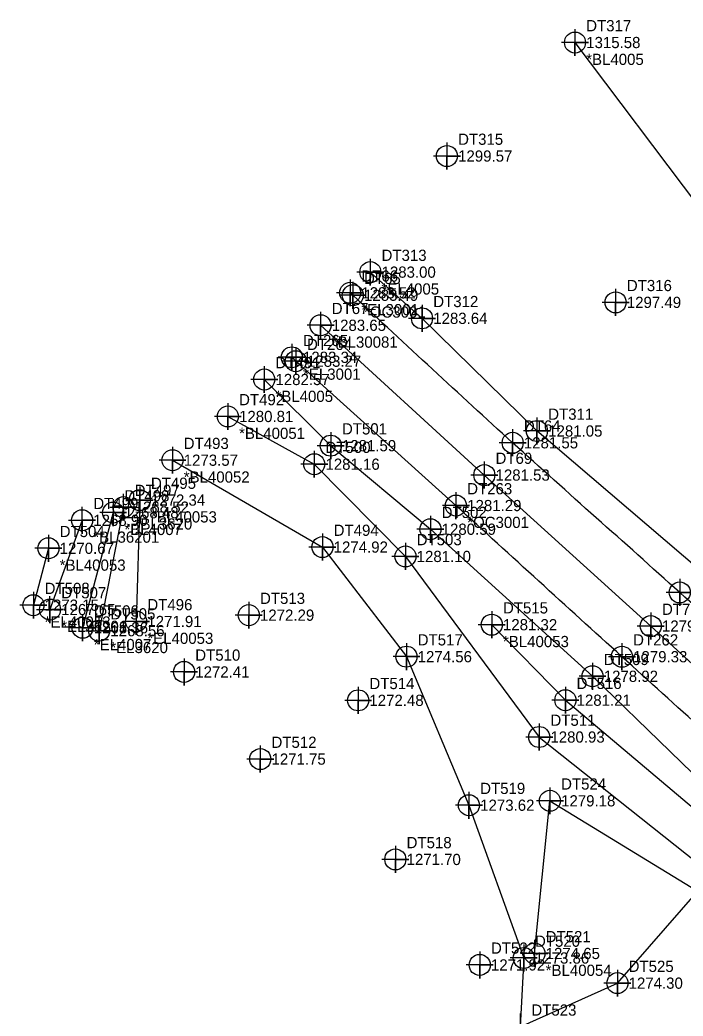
# Model space of a CAD drawing. Extents: x 1391270 to 1392151, y 960049 to 960667.
# Drawn here: x 1391269.8 to 1391417.5, y 960444.8 to 960666.9 of the extents above; entities that cross this region are included whole.
import ezdxf

# ---------------------------------------------------------------- set-up
doc = ezdxf.new("R2010")
doc.units = 0
for name, color, linetype in [('Exist DTM Breakline', 7, 'Continuous'), ('Exist DTM Breakline Cogo Comment', 7, 'Continuous'), ('Exist DTM Breakline Cogo Elevation', 7, 'Continuous'), ('Exist DTM Breakline Cogo Number', 7, 'Continuous'), ('Exist DTM Breakline Cogo Point CELL', 7, 'Continuous'), ('Exist DTM Breakline Underwater', 7, 'Continuous'), ('Exist DTM Breakline Underwater Cogo Comment', 7, 'Continuous'), ('Exist DTM Breakline Underwater Cogo Elevation', 7, 'Continuous'), ('Exist DTM Breakline Underwater Cogo Number', 7, 'Continuous'), ('Exist DTM Breakline Underwater Cogo Point CELL', 7, 'Continuous'), ('Exist DTM Crownline', 7, 'Continuous'), ('Exist DTM Crownline Cogo Comment', 7, 'Continuous'), ('Exist DTM Crownline Cogo Elevation', 7, 'Continuous'), ('Exist DTM Crownline Cogo Number', 7, 'Continuous'), ('Exist DTM Crownline Cogo Point CELL', 7, 'Continuous'), ('Exist DTM Regular Point CELL', 7, 'Continuous'), ('Exist DTM Regular Point Cogo Elevation', 7, 'Continuous'), ('Exist DTM Regular Point Cogo Number', 7, 'Continuous'), ('Exist Hydro Stream or Body of Water', 7, 'Continuous'), ('Exist Hydro Stream or Body of Water Cogo Comment', 7, 'Continuous'), ('Exist Hydro Stream or Body of Water Cogo Elevation', 7, 'Continuous'), ('Exist Hydro Stream or Body of Water Cogo Number', 7, 'Continuous'), ('Exist Hydro Stream or Body of Water Cogo Point CELL', 7, 'Continuous'), ('Exist Roads EOP', 7, 'Continuous'), ('Exist Roads EOP Cogo Comment', 7, 'Continuous'), ('Exist Roads EOP Cogo Elevation', 7, 'Continuous'), ('Exist Roads EOP Cogo Number', 7, 'Continuous'), ('Exist Roads EOP Cogo Point CELL', 7, 'Continuous')]:
    doc.layers.add(name, color=color, linetype=linetype)

msp = doc.modelspace()

# ---------------------------------------------------------------- linework, layer by layer
at = {"layer": 'Exist DTM Breakline'}
for p, q in [((1391296.492, 960559.828), (1391295.697, 960532.764)), ((1391276.164, 960549.078), (1391272.813, 960536.395))]:
    msp.add_line(p, q, dxfattribs=at)
for points in [[(1391393.449, 960661.814), (1391420.927, 960625.274), (1391436.139, 960609.727), (1391454.255, 960579.709), (1391474.064, 960542.237), (1391491.205, 960517.974), (1391488.925, 960510.22), (1391503.285, 960493.748), (1391518.522, 960484.392), (1391548.09, 960503.995), (1391563.385, 960512.482)], [(1391572.148, 960404.532), (1391566.45, 960414.023), (1391560.493, 960420.45), (1391551.134, 960422.515), (1391527.127, 960450.418), (1391519.65, 960459.266), (1391497.478, 960479.87), (1391479.684, 960499.497), (1391463.962, 960505.846), (1391421.736, 960543.837), (1391384.984, 960575.223), (1391359.376, 960600.331), (1391347.861, 960610.635)], [(1391324.233, 960586.705), (1391339.042, 960571.952), (1391361.254, 960553.328), (1391397.359, 960520.55), (1391431.984, 960487.022), (1391447.858, 960468.977), (1391469.387, 960439.951), (1391481.042, 960400.574)], [(1391316.128, 960578.463), (1391335.373, 960567.825), (1391355.688, 960547.259), (1391385.482, 960507.01), (1391423.359, 960476.875), (1391439.432, 960458.285), (1391460.969, 960427.473), (1391472.339, 960397.865), (1391475.509, 960385.212), (1391483.88, 960383.187), (1391486.523, 960363.38), (1391492.773, 960311.276)], [(1391303.798, 960568.714), (1391337.195, 960549.348), (1391355.915, 960524.922), (1391369.834, 960491.808), (1391382.04, 960457.756), (1391381.24, 960442.404), (1391402.896, 960452.148), (1391420.738, 960472.565), (1391439.191, 960450.264), (1391454.114, 960420.78), (1391463.153, 960401.998), (1391468.38, 960380.734), (1391451.764, 960376.78), (1391432.731, 960383.561)], [(1391374.906, 960532.045), (1391391.307, 960515.216), (1391429.365, 960483.152), (1391444, 960465.435), (1391465.005, 960433.545)], [(1391384.425, 960458.766), (1391387.861, 960492.79), (1391420.701, 960472.719)]]:
    msp.add_lwpolyline(points, dxfattribs=at)
at = {"layer": 'Exist DTM Breakline Cogo Point CELL'}
for points in [[(1391393.449, 960664.814), (1391393.449, 960658.814), (1391393.449, 960661.814), (1391396.449, 960661.814), (1391390.449, 960661.814)], [(1391347.861, 960613.635), (1391347.861, 960607.635), (1391347.861, 960610.635), (1391350.861, 960610.635), (1391344.861, 960610.635)], [(1391359.376, 960603.331), (1391359.376, 960597.331), (1391359.376, 960600.331), (1391362.376, 960600.331), (1391356.376, 960600.331)], [(1391324.233, 960589.705), (1391324.233, 960583.705), (1391324.233, 960586.705), (1391327.233, 960586.705), (1391321.233, 960586.705)], [(1391316.128, 960581.463), (1391316.128, 960575.463), (1391316.128, 960578.463), (1391319.128, 960578.463), (1391313.128, 960578.463)], [(1391384.984, 960578.223), (1391384.984, 960572.223), (1391384.984, 960575.223), (1391387.984, 960575.223), (1391381.984, 960575.223)], [(1391339.042, 960574.952), (1391339.042, 960568.952), (1391339.042, 960571.952), (1391342.042, 960571.952), (1391336.042, 960571.952)], [(1391303.798, 960571.714), (1391303.798, 960565.714), (1391303.798, 960568.714), (1391306.798, 960568.714), (1391300.798, 960568.714)], [(1391335.373, 960570.825), (1391335.373, 960564.825), (1391335.373, 960567.825), (1391338.373, 960567.825), (1391332.373, 960567.825)], [(1391296.492, 960562.828), (1391296.492, 960556.828), (1391296.492, 960559.828), (1391299.492, 960559.828), (1391293.492, 960559.828)], [(1391361.254, 960556.328), (1391361.254, 960550.328), (1391361.254, 960553.328), (1391364.254, 960553.328), (1391358.254, 960553.328)], [(1391276.164, 960552.078), (1391276.164, 960546.078), (1391276.164, 960549.078), (1391279.164, 960549.078), (1391273.164, 960549.078)], [(1391337.195, 960552.348), (1391337.195, 960546.348), (1391337.195, 960549.348), (1391340.195, 960549.348), (1391334.195, 960549.348)], [(1391355.688, 960550.259), (1391355.688, 960544.259), (1391355.688, 960547.259), (1391358.688, 960547.259), (1391352.688, 960547.259)], [(1391272.813, 960539.395), (1391272.813, 960533.395), (1391272.813, 960536.395), (1391275.813, 960536.395), (1391269.813, 960536.395)], [(1391295.697, 960535.764), (1391295.697, 960529.764), (1391295.697, 960532.764), (1391298.697, 960532.764), (1391292.697, 960532.764)], [(1391374.906, 960535.045), (1391374.906, 960529.045), (1391374.906, 960532.045), (1391377.906, 960532.045), (1391371.906, 960532.045)], [(1391355.915, 960527.922), (1391355.915, 960521.922), (1391355.915, 960524.922), (1391358.915, 960524.922), (1391352.915, 960524.922)], [(1391397.359, 960523.55), (1391397.359, 960517.55), (1391397.359, 960520.55), (1391400.359, 960520.55), (1391394.359, 960520.55)], [(1391391.307, 960518.216), (1391391.307, 960512.216), (1391391.307, 960515.216), (1391394.307, 960515.216), (1391388.307, 960515.216)], [(1391385.482, 960510.01), (1391385.482, 960504.01), (1391385.482, 960507.01), (1391388.482, 960507.01), (1391382.482, 960507.01)], [(1391387.861, 960495.79), (1391387.861, 960489.79), (1391387.861, 960492.79), (1391390.861, 960492.79), (1391384.861, 960492.79)], [(1391369.834, 960494.808), (1391369.834, 960488.808), (1391369.834, 960491.808), (1391372.834, 960491.808), (1391366.834, 960491.808)], [(1391382.04, 960460.756), (1391382.04, 960454.756), (1391382.04, 960457.756), (1391385.04, 960457.756), (1391379.04, 960457.756)], [(1391384.425, 960461.766), (1391384.425, 960455.766), (1391384.425, 960458.766), (1391387.425, 960458.766), (1391381.425, 960458.766)], [(1391402.896, 960455.148), (1391402.896, 960449.148), (1391402.896, 960452.148), (1391405.896, 960452.148), (1391399.896, 960452.148)], [(1391381.24, 960445.404), (1391381.24, 960439.404), (1391381.24, 960442.404), (1391384.24, 960442.404), (1391378.24, 960442.404)]]:
    msp.add_lwpolyline(points, dxfattribs=at)
for centre in [(1391393.449, 960661.814), (1391347.861, 960610.635), (1391359.376, 960600.331), (1391324.233, 960586.705), (1391316.128, 960578.463), (1391384.984, 960575.223), (1391339.042, 960571.952), (1391303.798, 960568.714), (1391335.373, 960567.825), (1391296.492, 960559.828), (1391361.254, 960553.328), (1391276.164, 960549.078), (1391337.195, 960549.348), (1391355.688, 960547.259), (1391272.813, 960536.395), (1391295.697, 960532.764), (1391374.906, 960532.045), (1391355.915, 960524.922), (1391397.359, 960520.55), (1391391.307, 960515.216), (1391385.482, 960507.01), (1391369.834, 960491.808), (1391387.861, 960492.79), (1391384.425, 960458.766), (1391382.04, 960457.756), (1391402.896, 960452.148)]:
    msp.add_circle(centre, 2.344, dxfattribs=at)
at = {"layer": 'Exist DTM Breakline Underwater'}
msp.add_line((1391290.577, 960557.031), (1391283.765, 960531.369), dxfattribs=at)
at = {"layer": 'Exist DTM Breakline Underwater Cogo Point CELL'}
for points in [[(1391290.577, 960560.031), (1391290.577, 960554.031), (1391290.577, 960557.031), (1391293.577, 960557.031), (1391287.577, 960557.031)], [(1391283.765, 960534.369), (1391283.765, 960528.369), (1391283.765, 960531.369), (1391286.765, 960531.369), (1391280.765, 960531.369)]]:
    msp.add_lwpolyline(points, dxfattribs=at)
for centre in [(1391290.577, 960557.031), (1391283.765, 960531.369)]:
    msp.add_circle(centre, 2.344, dxfattribs=at)
at = {"layer": 'Exist DTM Crownline'}
msp.add_lwpolyline([(1391336.775, 960598.787), (1391373.255, 960565.397), (1391410.328, 960531.742), (1391446.425, 960498.79), (1391483.147, 960465.095), (1391520.03, 960431.473), (1391553.996, 960400.745), (1391556.572, 960398.448)], dxfattribs=at)
at = {"layer": 'Exist DTM Crownline Cogo Point CELL'}
for points in [[(1391336.775, 960601.787), (1391336.775, 960595.787), (1391336.775, 960598.787), (1391339.775, 960598.787), (1391333.775, 960598.787)], [(1391373.255, 960568.397), (1391373.255, 960562.397), (1391373.255, 960565.397), (1391376.255, 960565.397), (1391370.255, 960565.397)], [(1391410.328, 960534.742), (1391410.328, 960528.742), (1391410.328, 960531.742), (1391413.328, 960531.742), (1391407.328, 960531.742)]]:
    msp.add_lwpolyline(points, dxfattribs=at)
for centre in [(1391336.775, 960598.787), (1391373.255, 960565.397), (1391410.328, 960531.742)]:
    msp.add_circle(centre, 2.344, dxfattribs=at)
at = {"layer": 'Exist DTM Regular Point CELL'}
for points in [[(1391364.919, 960639.509), (1391364.919, 960633.509), (1391364.919, 960636.509), (1391367.919, 960636.509), (1391361.919, 960636.509)], [(1391402.503, 960606.894), (1391402.503, 960600.894), (1391402.503, 960603.894), (1391405.503, 960603.894), (1391399.503, 960603.894)], [(1391320.789, 960537.174), (1391320.789, 960531.174), (1391320.789, 960534.174), (1391323.789, 960534.174), (1391317.789, 960534.174)], [(1391306.365, 960524.519), (1391306.365, 960518.519), (1391306.365, 960521.519), (1391309.365, 960521.519), (1391303.365, 960521.519)], [(1391345.154, 960518.187), (1391345.154, 960512.187), (1391345.154, 960515.187), (1391348.154, 960515.187), (1391342.154, 960515.187)], [(1391323.35, 960505.093), (1391323.35, 960499.093), (1391323.35, 960502.093), (1391326.35, 960502.093), (1391320.35, 960502.093)], [(1391353.438, 960482.726), (1391353.438, 960476.726), (1391353.438, 960479.726), (1391356.438, 960479.726), (1391350.438, 960479.726)], [(1391372.231, 960459.21), (1391372.231, 960453.21), (1391372.231, 960456.21), (1391375.231, 960456.21), (1391369.231, 960456.21)]]:
    msp.add_lwpolyline(points, dxfattribs=at)
for centre in [(1391364.919, 960636.509), (1391402.503, 960603.894), (1391320.789, 960534.174), (1391306.365, 960521.519), (1391345.154, 960515.187), (1391323.35, 960502.093), (1391353.438, 960479.726), (1391372.231, 960456.21)]:
    msp.add_circle(centre, 2.344, dxfattribs=at)
at = {"layer": 'Exist Hydro Stream or Body of Water'}
for p, q in [((1391292.872, 960558.252), (1391287.45, 960530.713)), ((1391283.66, 960555.319), (1391276.506, 960535.422))]:
    msp.add_line(p, q, dxfattribs=at)
at = {"layer": 'Exist Hydro Stream or Body of Water Cogo Point CELL'}
for points in [[(1391289.872, 960558.252), (1391295.872, 960558.252), (1391292.872, 960558.252), (1391292.872, 960555.252), (1391292.872, 960561.252)], [(1391280.66, 960555.319), (1391286.66, 960555.319), (1391283.66, 960555.319), (1391283.66, 960552.319), (1391283.66, 960558.319)], [(1391273.506, 960535.422), (1391279.506, 960535.422), (1391276.506, 960535.422), (1391276.506, 960532.422), (1391276.506, 960538.422)], [(1391284.45, 960530.713), (1391290.45, 960530.713), (1391287.45, 960530.713), (1391287.45, 960527.713), (1391287.45, 960533.713)]]:
    msp.add_lwpolyline(points, dxfattribs=at)
for centre in [(1391292.872, 960558.252), (1391283.66, 960555.319), (1391276.506, 960535.422), (1391287.45, 960530.713)]:
    msp.add_circle(centre, 2.344, dxfattribs=at)
at = {"layer": 'Exist Roads EOP'}
msp.add_line((1391343.959, 960605.485), (1391343.365, 960606.024), dxfattribs=at)
msp.add_lwpolyline([(1391366.94, 960558.603), (1391331.255, 960590.777), (1391330.371, 960591.644)], dxfattribs=at)
for points in [[(1391558.507, 960409.653), (1391527.113, 960438.384), (1391489.556, 960472.216), (1391453.007, 960506.097), (1391416.783, 960539.246), (1391379.565, 960572.597), (1391343.959, 960605.485)], [(1391497.16, 960311.857), (1391494.199, 960339.333), (1391490.437, 960370.67), (1391484.795, 960409.189), (1391479.352, 960429.561), (1391471.345, 960448.702), (1391460.843, 960466.873), (1391449.093, 960483.056), (1391440.139, 960491.898), (1391403.899, 960524.912), (1391366.94, 960558.603)]]:
    msp.add_spline(points, degree=3, dxfattribs=at)
at = {"layer": 'Exist Roads EOP Cogo Point CELL'}
for points in [[(1391343.365, 960609.024), (1391343.365, 960603.024), (1391343.365, 960606.024), (1391346.365, 960606.024), (1391340.365, 960606.024)], [(1391343.959, 960608.485), (1391343.959, 960602.485), (1391343.959, 960605.485), (1391346.959, 960605.485), (1391340.959, 960605.485)], [(1391330.371, 960594.644), (1391330.371, 960588.644), (1391330.371, 960591.644), (1391333.371, 960591.644), (1391327.371, 960591.644)], [(1391331.255, 960593.777), (1391331.255, 960587.777), (1391331.255, 960590.777), (1391334.255, 960590.777), (1391328.255, 960590.777)], [(1391379.565, 960575.597), (1391379.565, 960569.597), (1391379.565, 960572.597), (1391382.565, 960572.597), (1391376.565, 960572.597)], [(1391366.94, 960561.603), (1391366.94, 960555.603), (1391366.94, 960558.603), (1391369.94, 960558.603), (1391363.94, 960558.603)], [(1391416.783, 960542.246), (1391416.783, 960536.246), (1391416.783, 960539.246), (1391419.783, 960539.246), (1391413.783, 960539.246)], [(1391403.899, 960527.912), (1391403.899, 960521.912), (1391403.899, 960524.912), (1391406.899, 960524.912), (1391400.899, 960524.912)]]:
    msp.add_lwpolyline(points, dxfattribs=at)
for centre in [(1391343.365, 960606.024), (1391343.959, 960605.485), (1391330.371, 960591.644), (1391331.255, 960590.777), (1391379.565, 960572.597), (1391366.94, 960558.603), (1391416.783, 960539.246), (1391403.899, 960524.912)]:
    msp.add_circle(centre, 2.344, dxfattribs=at)

# ---------------------------------------------------------------- texts
at = {"layer": 'Exist DTM Breakline Cogo Comment'}
for s, p in [('*BL4005', (1391395.949, 960656.814)), ('*EL4005', (1391350.361, 960605.635)), ('*BL4005', (1391326.733, 960581.705)), ('*BL40051', (1391318.628, 960573.463)), ('*BL40052', (1391306.298, 960563.714)), ('*BL40053', (1391298.992, 960554.828)), ('*BL40053', (1391278.664, 960544.078)), ('*EL40053', (1391275.313, 960531.395)), ('*EL40053', (1391298.197, 960527.764)), ('*BL40053', (1391377.406, 960527.045)), ('*BL40054', (1391386.925, 960453.766))]:
    msp.add_text(s, height=2.5, dxfattribs=at).set_placement(p)
at = {"layer": 'Exist DTM Breakline Cogo Elevation'}
for s, p in [('1315.58', (1391395.949, 960660.564)), ('1283.00', (1391350.361, 960609.385)), ('1283.64', (1391361.876, 960599.081)), ('1282.57', (1391326.733, 960585.455)), ('1280.81', (1391318.628, 960577.213)), ('1281.05', (1391387.484, 960573.973)), ('1281.59', (1391341.542, 960570.702)), ('1273.57', (1391306.298, 960567.464)), ('1281.16', (1391337.873, 960566.575)), ('1272.34', (1391298.992, 960558.578)), ('1280.59', (1391363.754, 960552.078)), ('1270.67', (1391278.664, 960547.828)), ('1274.92', (1391339.695, 960548.098)), ('1281.10', (1391358.188, 960546.009)), ('1273.15', (1391275.313, 960535.145)), ('1271.91', (1391298.197, 960531.514)), ('1281.32', (1391377.406, 960530.795)), ('1274.56', (1391358.415, 960523.672)), ('1278.92', (1391399.859, 960519.3)), ('1281.21', (1391393.807, 960513.966)), ('1280.93', (1391387.982, 960505.76)), ('1279.18', (1391390.361, 960491.54)), ('1273.62', (1391372.334, 960490.558)), ('1273.86', (1391384.54, 960456.506)), ('1274.65', (1391386.925, 960457.516)), ('1274.30', (1391405.396, 960450.898))]:
    msp.add_text(s, height=2.5, dxfattribs=at).set_placement(p)
at = {"layer": 'Exist DTM Breakline Cogo Number'}
for s, p in [('DT317', (1391395.949, 960664.314)), ('DT313', (1391350.361, 960613.135)), ('DT312', (1391361.876, 960602.831)), ('DT491', (1391326.733, 960589.205)), ('DT492', (1391318.628, 960580.963)), ('DT311', (1391387.484, 960577.723)), ('DT501', (1391341.542, 960574.452)), ('DT493', (1391306.298, 960571.214)), ('DT500', (1391337.873, 960570.325)), ('DT495', (1391298.992, 960562.328)), ('DT502', (1391363.754, 960555.828)), ('DT504', (1391278.664, 960551.578)), ('DT494', (1391339.695, 960551.848)), ('DT503', (1391358.188, 960549.759)), ('DT508', (1391275.313, 960538.895)), ('DT496', (1391298.197, 960535.264)), ('DT515', (1391377.406, 960534.545)), ('DT517', (1391358.415, 960527.422)), ('DT509', (1391399.859, 960523.05)), ('DT516', (1391393.807, 960517.716)), ('DT511', (1391387.982, 960509.51)), ('DT519', (1391372.334, 960494.308)), ('DT524', (1391390.361, 960495.29)), ('DT520', (1391384.54, 960460.256)), ('DT521', (1391386.925, 960461.266)), ('DT525', (1391405.396, 960454.648)), ('DT523', (1391383.74, 960444.904))]:
    msp.add_text(s, height=2.5, dxfattribs=at).set_placement(p)
at = {"layer": 'Exist DTM Breakline Underwater Cogo Comment'}
for s, p in [('*BL4007', (1391293.077, 960552.031)), ('*EL4007', (1391286.265, 960526.369))]:
    msp.add_text(s, height=2.5, dxfattribs=at).set_placement(p)
at = {"layer": 'Exist DTM Breakline Underwater Cogo Elevation'}
for s, p in [('1268.48', (1391293.077, 960555.781)), ('1268.36', (1391286.265, 960530.119))]:
    msp.add_text(s, height=2.5, dxfattribs=at).set_placement(p)
at = {"layer": 'Exist DTM Breakline Underwater Cogo Number'}
for s, p in [('DT498', (1391293.077, 960559.531)), ('DT506', (1391286.265, 960533.869))]:
    msp.add_text(s, height=2.5, dxfattribs=at).set_placement(p)
at = {"layer": 'Exist DTM Crownline Cogo Comment'}
msp.add_text('*BL30081', height=2.5, dxfattribs=at).set_placement((1391339.275, 960593.787))
at = {"layer": 'Exist DTM Crownline Cogo Elevation'}
for s, p in [('1283.65', (1391339.275, 960597.537)), ('1281.53', (1391375.755, 960564.147)), ('1279.46', (1391412.828, 960530.492))]:
    msp.add_text(s, height=2.5, dxfattribs=at).set_placement(p)
at = {"layer": 'Exist DTM Crownline Cogo Number'}
for s, p in [('DT67', (1391339.275, 960601.287)), ('DT69', (1391375.755, 960567.897)), ('DT70', (1391412.828, 960534.242))]:
    msp.add_text(s, height=2.5, dxfattribs=at).set_placement(p)
at = {"layer": 'Exist DTM Regular Point Cogo Elevation'}
for s, p in [('1299.57', (1391367.419, 960635.259)), ('1297.49', (1391405.003, 960602.644)), ('1272.29', (1391323.289, 960532.924)), ('1272.41', (1391308.865, 960520.269)), ('1272.48', (1391347.654, 960513.937)), ('1271.75', (1391325.85, 960500.843)), ('1271.70', (1391355.938, 960478.476)), ('1271.92', (1391374.731, 960454.96))]:
    msp.add_text(s, height=2.5, dxfattribs=at).set_placement(p)
at = {"layer": 'Exist DTM Regular Point Cogo Number'}
for s, p in [('DT315', (1391367.419, 960639.009)), ('DT316', (1391405.003, 960606.394)), ('DT513', (1391323.289, 960536.674)), ('DT510', (1391308.865, 960524.019)), ('DT514', (1391347.654, 960517.687)), ('DT512', (1391325.85, 960504.593)), ('DT518', (1391355.938, 960482.226)), ('DT522', (1391374.731, 960458.71))]:
    msp.add_text(s, height=2.5, dxfattribs=at).set_placement(p)
at = {"layer": 'Exist Hydro Stream or Body of Water Cogo Comment'}
for s, p in [('*BL3620', (1391295.372, 960553.252)), ('*BL36201', (1391286.16, 960550.319)), ('*EL36201', (1391279.006, 960530.422)), ('*EL3620', (1391289.95, 960525.713))]:
    msp.add_text(s, height=2.5, dxfattribs=at).set_placement(p)
at = {"layer": 'Exist Hydro Stream or Body of Water Cogo Elevation'}
for s, p in [('1268.52', (1391295.372, 960557.002)), ('1268.90', (1391286.16, 960554.069)), ('1267.65', (1391279.006, 960534.172)), ('1268.56', (1391289.95, 960529.463))]:
    msp.add_text(s, height=2.5, dxfattribs=at).set_placement(p)
at = {"layer": 'Exist Hydro Stream or Body of Water Cogo Number'}
for s, p in [('DT497', (1391295.372, 960560.752)), ('DT499', (1391286.16, 960557.819)), ('DT507', (1391279.006, 960537.922)), ('DT505', (1391289.95, 960533.213))]:
    msp.add_text(s, height=2.5, dxfattribs=at).set_placement(p)
at = {"layer": 'Exist Roads EOP Cogo Comment'}
for s, p in [('*EL3001', (1391345.865, 960601.024)), ('*OC3001', (1391346.459, 960600.485)), ('*EL3001', (1391332.871, 960586.644)), ('*OC3001', (1391369.44, 960553.603))]:
    msp.add_text(s, height=2.5, dxfattribs=at).set_placement(p)
at = {"layer": 'Exist Roads EOP Cogo Elevation'}
for s, p in [('1283.52', (1391345.865, 960604.774)), ('1283.49', (1391346.459, 960604.235)), ('1283.34', (1391332.871, 960590.394)), ('1283.27', (1391333.755, 960589.527)), ('1281.55', (1391382.065, 960571.347)), ('1281.29', (1391369.44, 960557.353)), ('1279.33', (1391406.399, 960523.662))]:
    msp.add_text(s, height=2.5, dxfattribs=at).set_placement(p)
at = {"layer": 'Exist Roads EOP Cogo Number'}
for s, p in [('DT66', (1391345.865, 960608.524)), ('DT65', (1391346.459, 960607.985)), ('DT265', (1391332.871, 960594.144)), ('DT264', (1391333.755, 960593.277)), ('DT64', (1391382.065, 960575.097)), ('DT263', (1391369.44, 960561.103)), ('DT262', (1391406.399, 960527.412))]:
    msp.add_text(s, height=2.5, dxfattribs=at).set_placement(p)

doc.saveas('drawing.dxf')
